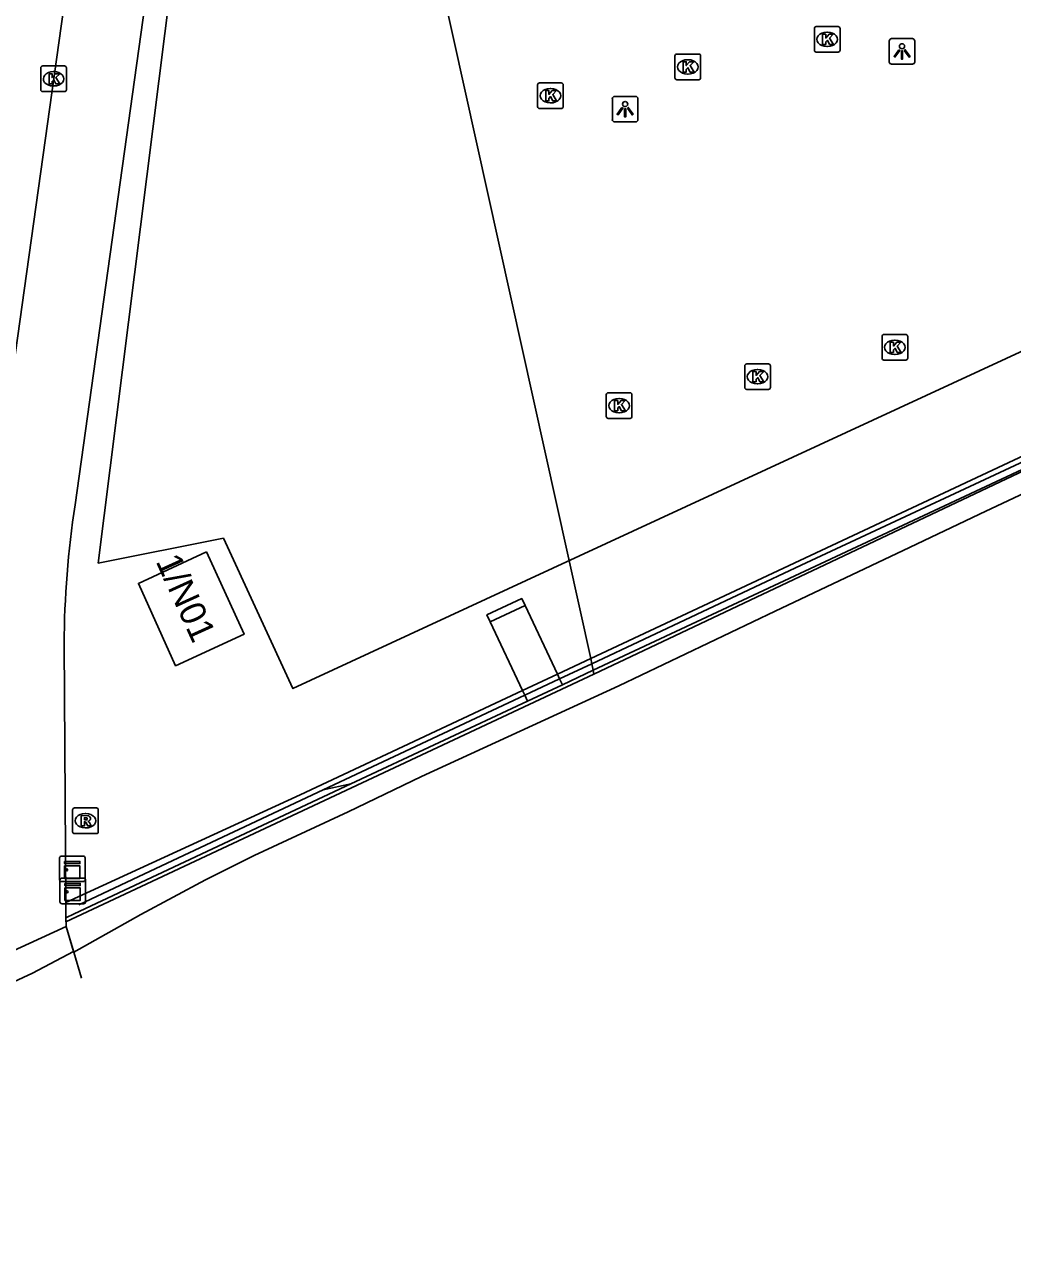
# Model space of a CAD drawing. Extents: x 160806 to 161707, y 383697 to 384148.
# Drawn here: x 161284.05 to 161322.57, y 383743.17 to 383791.51 of the extents above; entities that cross this region are included whole.
import ezdxf

# ---------------------------------------------------------------- set-up
doc = ezdxf.new("R2010")
doc.units = 0
for name, color, linetype in [('IMGEO_Dek', 7, 'Continuous'), ('IMGEO_Fietspad_open', 7, 'Continuous'), ('IMGEO_Groenvoorziening', 7, 'Continuous'), ('IMGEO_Hek', 7, 'Continuous'), ('IMGEO_Kast', 7, 'Continuous'), ('IMGEO_Kolk', 7, 'Continuous'), ('IMGEO_Lichtpunt', 7, 'Continuous'), ('IMGEO_Muur', 7, 'Continuous'), ('IMGEO_Pand', 7, 'Continuous'), ('IMGEO_Pand_nummerreeks', 7, 'Continuous'), ('IMGEO_Pand_vergunning_verleend', 7, 'Continuous'), ('IMGEO_Rioolput', 7, 'Continuous'), ('IMGEO_Spoorbaan_halfverhard', 7, 'Continuous'), ('IMGEO_Spoorbaan_open', 7, 'Continuous'), ('IMGEO_Terreindeel_gesloten', 7, 'Continuous'), ('IMGEO_Voetgangersgebied_open', 7, 'Continuous'), ('IMGEO_Voetpad_op_trap', 7, 'Continuous'), ('IMGEO_Voetpad_open', 7, 'Continuous')]:
    doc.layers.add(name, color=color, linetype=linetype)

msp = doc.modelspace()

# ---------------------------------------------------------------- linework, layer by layer
at = {"layer": 'IMGEO_Dek'}
msp.add_lwpolyline([(161302.206, 383768.201), (161303.47, 383765.52), (161303.556, 383765.337), (161303.663, 383765.111), (161305.021, 383765.747), (161304.913, 383765.977), (161304.828, 383766.158), (161303.562, 383768.841), (161303.434, 383769.112), (161302.078, 383768.472)], close=True, dxfattribs=at)
at = {"layer": 'IMGEO_Fietspad_open'}
msp.add_lwpolyline([(161288.857, 383815.733), (161288.794, 383815.268), (161282.95, 383773.511)], dxfattribs=at)
at = {"layer": 'IMGEO_Groenvoorziening'}
for points in [[(161306.227, 383766.312), (161344.529, 383784.251), (161345.081, 383784.51), (161345.678, 383784.79), (161353.357, 383788.389)], [(161302.206, 383768.201), (161303.562, 383768.841), (161303.434, 383769.112), (161302.078, 383768.472), (161302.206, 383768.201)], [(161306.126, 383766.767), (161304.828, 383766.158), (161303.47, 383765.52), (161294.794, 383761.449), (161285.649, 383757.252)], [(161306.17, 383766.569), (161306.126, 383766.767)], [(161285.653, 383756.655), (161285.978, 383756.8), (161296.767, 383761.881)]]:
    msp.add_lwpolyline(points, dxfattribs=at)
at = {"layer": 'IMGEO_Hek'}
for points in [[(161304.913, 383765.977), (161306.17, 383766.569), (161314.338, 383770.42), (161324.98, 383775.393), (161337.778, 383781.392), (161350.576, 383787.419), (161357.031, 383790.441), (161365.479, 383794.338), (161372.031, 383797.151), (161378.634, 383799.703), (161383.104, 383801.204), (161385.56, 383801.947)], [(161303.556, 383765.337), (161303.47, 383765.52), (161302.206, 383768.201), (161302.078, 383768.472), (161303.434, 383769.112), (161303.562, 383768.841), (161304.828, 383766.158), (161304.913, 383765.977)], [(161303.556, 383765.337), (161297.189, 383762.349), (161295.69, 383761.645), (161288.711, 383758.369), (161286.158, 383757.158)]]:
    msp.add_lwpolyline(points, dxfattribs=at)
at = {"layer": 'IMGEO_Kast'}
for p, q in [((161285.477, 383759.062), (161286.318, 383759.062)), ((161286.318, 383759.062), (161285.477, 383759.062)), ((161285.402, 383758.137), (161285.402, 383758.978)), ((161285.402, 383758.978), (161285.402, 383758.137)), ((161286.402, 383758.987), (161286.402, 383758.146)), ((161286.402, 383758.146), (161286.402, 383758.987)), ((161285.417, 383757.277), (161285.417, 383758.118)), ((161285.417, 383758.118), (161285.417, 383757.277)), ((161285.492, 383758.202), (161286.333, 383758.202)), ((161286.333, 383758.202), (161285.492, 383758.202)), ((161286.417, 383758.127), (161286.417, 383757.286)), ((161286.417, 383757.286), (161286.417, 383758.127)), ((161286.327, 383758.062), (161285.486, 383758.062)), ((161285.486, 383758.062), (161286.327, 383758.062)), ((161286.342, 383757.202), (161285.501, 383757.202)), ((161285.501, 383757.202), (161286.342, 383757.202))]:
    msp.add_line(p, q, dxfattribs=at)
for points in [[(161285.597, 383758.852), (161286.197, 383758.852), (161286.197, 383758.767), (161285.597, 383758.767), (161285.597, 383758.852)], [(161285.597, 383758.677), (161286.197, 383758.677), (161286.197, 383758.188), (161285.597, 383758.188), (161285.597, 383758.677)], [(161285.612, 383757.992), (161286.212, 383757.992), (161286.212, 383757.907), (161285.612, 383757.907), (161285.612, 383757.992)], [(161285.612, 383757.817), (161286.212, 383757.817), (161286.212, 383757.328), (161285.612, 383757.328), (161285.612, 383757.817)]]:
    msp.add_lwpolyline(points, dxfattribs=at)
for centre in [(161285.681, 383758.526), (161285.696, 383757.666)]:
    msp.add_circle(centre, 0.0377, dxfattribs=at)
for centre, start, end in [((161285.48, 383758.984), 92.4484, 184.2845), ((161285.48, 383758.984), 92.4484, 184.2845), ((161286.324, 383758.984), 2.4484, 94.2845), ((161286.324, 383758.984), 2.4484, 94.2845), ((161285.48, 383758.14), 182.4484, 274.2845), ((161285.48, 383758.14), 182.4484, 274.2845), ((161285.495, 383758.124), 92.4484, 184.2845), ((161285.495, 383758.124), 92.4484, 184.2845), ((161286.324, 383758.14), 272.4484, 4.2845), ((161286.324, 383758.14), 272.4484, 4.2845), ((161286.339, 383758.124), 2.4484, 94.2845), ((161286.339, 383758.124), 2.4484, 94.2845), ((161285.495, 383757.28), 182.4484, 274.2845), ((161285.495, 383757.28), 182.4484, 274.2845), ((161286.339, 383757.28), 272.4484, 4.2845), ((161286.339, 383757.28), 272.4484, 4.2845)]:
    msp.add_arc(centre, 0.0779, start, end, dxfattribs=at)
at = {"layer": 'IMGEO_Kolk'}
for p, q in [((161314.927, 383791.444), (161315.779, 383791.444)), ((161314.852, 383790.518), (161314.852, 383791.37)), ((161315.34, 383791.224), (161315.365, 383791.224)), ((161315.853, 383791.37), (161315.853, 383790.518)), ((161315.363, 383790.664), (161315.338, 383790.664)), ((161309.411, 383789.442), (161309.411, 383790.294)), ((161309.486, 383790.368), (161310.338, 383790.368)), ((161309.899, 383790.148), (161309.924, 383790.148)), ((161310.412, 383790.294), (161310.412, 383789.442)), ((161315.779, 383790.444), (161314.927, 383790.444)), ((161284.671, 383788.977), (161284.671, 383789.829)), ((161284.746, 383789.903), (161285.598, 383789.903)), ((161285.159, 383789.683), (161285.184, 383789.683)), ((161285.672, 383789.829), (161285.672, 383788.977)), ((161309.922, 383789.588), (161309.897, 383789.588)), ((161285.182, 383789.123), (161285.157, 383789.123)), ((161304.052, 383788.316), (161304.052, 383789.168)), ((161304.127, 383789.242), (161304.979, 383789.242)), ((161304.54, 383789.022), (161304.565, 383789.022)), ((161305.053, 383789.168), (161305.053, 383788.316)), ((161310.338, 383789.368), (161309.486, 383789.368)), ((161285.598, 383788.903), (161284.746, 383788.903)), ((161304.979, 383788.242), (161304.127, 383788.242)), ((161304.563, 383788.462), (161304.538, 383788.462)), ((161317.491, 383778.495), (161317.491, 383779.347)), ((161317.566, 383779.421), (161318.418, 383779.421)), ((161318.492, 383779.347), (161318.492, 383778.495)), ((161317.979, 383779.201), (161318.004, 383779.201)), ((161318.418, 383778.421), (161317.566, 383778.421)), ((161318.002, 383778.641), (161317.977, 383778.641)), ((161312.135, 383777.349), (161312.135, 383778.201)), ((161312.21, 383778.275), (161313.062, 383778.275)), ((161312.623, 383778.055), (161312.648, 383778.055)), ((161313.136, 383778.201), (161313.136, 383777.349)), ((161312.646, 383777.495), (161312.621, 383777.495)), ((161306.733, 383776.218), (161306.733, 383777.07)), ((161306.808, 383777.144), (161307.66, 383777.144)), ((161307.734, 383777.07), (161307.734, 383776.218)), ((161313.062, 383777.275), (161312.21, 383777.275)), ((161307.221, 383776.924), (161307.246, 383776.924)), ((161307.66, 383776.144), (161306.808, 383776.144)), ((161307.244, 383776.364), (161307.219, 383776.364))]:
    msp.add_line(p, q, dxfattribs=at)
for points in [[(161314.927, 383791.444), (161315.779, 383791.444)], [(161314.852, 383790.518), (161314.852, 383791.37)], [(161315.173, 383791.144), (161315.296, 383791.144), (161315.296, 383790.993), (161315.426, 383791.144), (161315.59, 383791.144), (161315.444, 383790.993), (161315.597, 383790.744), (161315.445, 383790.744), (161315.36, 383790.908), (161315.296, 383790.841), (161315.296, 383790.744), (161315.173, 383790.744), (161315.173, 383791.144)], [(161315.853, 383791.37), (161315.853, 383790.518)], [(161309.411, 383789.442), (161309.411, 383790.294)], [(161309.486, 383790.368), (161310.338, 383790.368)], [(161309.732, 383790.068), (161309.855, 383790.068), (161309.855, 383789.917), (161309.985, 383790.068), (161310.149, 383790.068), (161310.003, 383789.917), (161310.156, 383789.668), (161310.004, 383789.668), (161309.919, 383789.832), (161309.855, 383789.765), (161309.855, 383789.668), (161309.732, 383789.668), (161309.732, 383790.068)], [(161310.412, 383790.294), (161310.412, 383789.442)], [(161315.779, 383790.444), (161314.927, 383790.444)], [(161284.671, 383788.977), (161284.671, 383789.829)], [(161284.746, 383789.903), (161285.598, 383789.903)], [(161284.992, 383789.603), (161285.115, 383789.603), (161285.115, 383789.452), (161285.245, 383789.603), (161285.409, 383789.603), (161285.263, 383789.452), (161285.416, 383789.203), (161285.264, 383789.203), (161285.179, 383789.367), (161285.115, 383789.3), (161285.115, 383789.203), (161284.992, 383789.203), (161284.992, 383789.603)], [(161285.672, 383789.829), (161285.672, 383788.977)], [(161304.052, 383788.316), (161304.052, 383789.168)], [(161304.127, 383789.242), (161304.979, 383789.242)], [(161305.053, 383789.168), (161305.053, 383788.316)], [(161310.338, 383789.368), (161309.486, 383789.368)], [(161285.598, 383788.903), (161284.746, 383788.903)], [(161304.373, 383788.942), (161304.496, 383788.942), (161304.496, 383788.791), (161304.626, 383788.942), (161304.79, 383788.942), (161304.644, 383788.791), (161304.797, 383788.542), (161304.645, 383788.542), (161304.56, 383788.706), (161304.496, 383788.639), (161304.496, 383788.542), (161304.373, 383788.542), (161304.373, 383788.942)], [(161304.979, 383788.242), (161304.127, 383788.242)], [(161317.491, 383778.495), (161317.491, 383779.347)], [(161317.566, 383779.421), (161318.418, 383779.421)], [(161318.492, 383779.347), (161318.492, 383778.495)], [(161317.812, 383779.121), (161317.935, 383779.121), (161317.935, 383778.97), (161318.065, 383779.121), (161318.229, 383779.121), (161318.083, 383778.97), (161318.236, 383778.721), (161318.084, 383778.721), (161317.999, 383778.885), (161317.935, 383778.818), (161317.935, 383778.721), (161317.812, 383778.721), (161317.812, 383779.121)], [(161318.418, 383778.421), (161317.566, 383778.421)], [(161312.135, 383777.349), (161312.135, 383778.201)], [(161312.21, 383778.275), (161313.062, 383778.275)], [(161312.456, 383777.975), (161312.579, 383777.975), (161312.579, 383777.824), (161312.709, 383777.975), (161312.873, 383777.975), (161312.727, 383777.824), (161312.88, 383777.575), (161312.728, 383777.575), (161312.643, 383777.739), (161312.579, 383777.672), (161312.579, 383777.575), (161312.456, 383777.575), (161312.456, 383777.975)], [(161313.136, 383778.201), (161313.136, 383777.349)], [(161306.733, 383776.218), (161306.733, 383777.07)], [(161306.808, 383777.144), (161307.66, 383777.144)], [(161307.734, 383777.07), (161307.734, 383776.218)], [(161313.062, 383777.275), (161312.21, 383777.275)], [(161307.054, 383776.844), (161307.177, 383776.844), (161307.177, 383776.693), (161307.307, 383776.844), (161307.471, 383776.844), (161307.325, 383776.693), (161307.478, 383776.444), (161307.326, 383776.444), (161307.241, 383776.608), (161307.177, 383776.541), (161307.177, 383776.444), (161307.054, 383776.444), (161307.054, 383776.844)], [(161307.66, 383776.144), (161306.808, 383776.144)]]:
    msp.add_lwpolyline(points, dxfattribs=at)
for centre, start, end in [((161314.929, 383791.368), 91.552, 178.448), ((161314.929, 383791.368), 91.552, 178.448), ((161315.777, 383791.368), 1.552, 88.448), ((161315.777, 383791.368), 1.552, 88.448), ((161314.929, 383790.52), 181.552, 268.448), ((161314.929, 383790.52), 181.552, 268.448), ((161315.777, 383790.52), 271.552, 358.448), ((161315.777, 383790.52), 271.552, 358.448), ((161309.488, 383790.292), 91.552, 178.448), ((161309.488, 383790.292), 91.552, 178.448), ((161310.336, 383790.292), 1.552, 88.448), ((161310.336, 383790.292), 1.552, 88.448), ((161284.748, 383789.827), 91.552, 178.448), ((161284.748, 383789.827), 91.552, 178.448), ((161285.596, 383789.827), 1.552, 88.448), ((161285.596, 383789.827), 1.552, 88.448), ((161304.129, 383789.166), 91.552, 178.448), ((161304.129, 383789.166), 91.552, 178.448), ((161304.977, 383789.166), 1.552, 88.448), ((161304.977, 383789.166), 1.552, 88.448), ((161309.488, 383789.444), 181.552, 268.448), ((161309.488, 383789.444), 181.552, 268.448), ((161310.336, 383789.444), 271.552, 358.448), ((161310.336, 383789.444), 271.552, 358.448), ((161284.748, 383788.979), 181.552, 268.448), ((161284.748, 383788.979), 181.552, 268.448), ((161285.596, 383788.979), 271.552, 358.448), ((161285.596, 383788.979), 271.552, 358.448), ((161304.129, 383788.318), 181.552, 268.448), ((161304.129, 383788.318), 181.552, 268.448), ((161304.977, 383788.318), 271.552, 358.448), ((161304.977, 383788.318), 271.552, 358.448), ((161317.568, 383779.345), 91.552, 178.448), ((161317.568, 383779.345), 91.552, 178.448), ((161318.416, 383779.345), 1.552, 88.448), ((161318.416, 383779.345), 1.552, 88.448), ((161317.568, 383778.497), 181.552, 268.448), ((161317.568, 383778.497), 181.552, 268.448), ((161318.416, 383778.497), 271.552, 358.448), ((161318.416, 383778.497), 271.552, 358.448), ((161312.212, 383778.199), 91.552, 178.448), ((161312.212, 383778.199), 91.552, 178.448), ((161313.06, 383778.199), 1.552, 88.448), ((161313.06, 383778.199), 1.552, 88.448), ((161306.81, 383777.068), 91.552, 178.448), ((161306.81, 383777.068), 91.552, 178.448), ((161307.658, 383777.068), 1.552, 88.448), ((161307.658, 383777.068), 1.552, 88.448), ((161312.212, 383777.351), 181.552, 268.448), ((161312.212, 383777.351), 181.552, 268.448), ((161313.06, 383777.351), 271.552, 358.448), ((161313.06, 383777.351), 271.552, 358.448), ((161306.81, 383776.22), 181.552, 268.448), ((161306.81, 383776.22), 181.552, 268.448), ((161307.658, 383776.22), 271.552, 358.448), ((161307.658, 383776.22), 271.552, 358.448)]:
    msp.add_arc(centre, 0.0765, start, end, dxfattribs=at)
for centre, major_axis, ratio, start_param, end_param in [((161315.339, 383790.944), (-0.387, 0.002), 0.722429, 4.712389, 7.853982), ((161315.364, 383790.944), (-0.39, 0.002), 0.717154, 1.570796, 4.712389), ((161309.898, 383789.868), (-0.387, 0.002), 0.722429, 4.712389, 7.853982), ((161309.923, 383789.868), (-0.39, 0.002), 0.717154, 1.570796, 4.712389), ((161285.158, 383789.403), (-0.387, 0.002), 0.722429, 4.712389, 7.853982), ((161285.183, 383789.403), (-0.39, 0.002), 0.717154, 1.570796, 4.712389), ((161304.539, 383788.742), (-0.387, 0.002), 0.722429, 4.712389, 7.853982), ((161304.564, 383788.742), (-0.39, 0.002), 0.717154, 1.570796, 4.712389), ((161317.978, 383778.921), (-0.387, 0.002), 0.722429, 4.712389, 7.853982), ((161318.003, 383778.921), (-0.39, 0.002), 0.717154, 1.570796, 4.712389), ((161312.622, 383777.775), (-0.387, 0.002), 0.722429, 4.712389, 7.853982), ((161312.647, 383777.775), (-0.39, 0.002), 0.717154, 1.570796, 4.712389), ((161307.22, 383776.644), (-0.387, 0.002), 0.722429, 4.712389, 7.853982), ((161307.245, 383776.644), (-0.39, 0.002), 0.717154, 1.570796, 4.712389)]:
    msp.add_ellipse(centre, major_axis=major_axis, ratio=ratio, start_param=start_param, end_param=end_param, dxfattribs=at)
at = {"layer": 'IMGEO_Lichtpunt'}
for p, q in [((161318.673, 383790.971), (161317.865, 383790.971)), ((161318.673, 383790.971), (161317.865, 383790.971)), ((161317.771, 383790.876), (161317.771, 383790.069)), ((161317.771, 383790.876), (161317.771, 383790.069)), ((161318.767, 383790.069), (161318.767, 383790.876)), ((161318.767, 383790.069), (161318.767, 383790.876)), ((161317.865, 383789.975), (161318.673, 383789.975)), ((161317.865, 383789.975), (161318.673, 383789.975)), ((161306.969, 383788.621), (161306.969, 383787.814)), ((161306.969, 383788.621), (161306.969, 383787.814)), ((161307.871, 383788.716), (161307.063, 383788.716)), ((161307.871, 383788.716), (161307.063, 383788.716)), ((161307.965, 383787.814), (161307.965, 383788.621)), ((161307.965, 383787.814), (161307.965, 383788.621)), ((161307.063, 383787.72), (161307.871, 383787.72)), ((161307.063, 383787.72), (161307.871, 383787.72))]:
    msp.add_line(p, q, dxfattribs=at)
for points in [[(161318.145, 383790.54), (161318.184, 383790.512), (161317.996, 383790.25), (161317.958, 383790.277), (161318.145, 383790.54)], [(161318.247, 383790.492), (161318.294, 383790.492), (161318.294, 383790.17), (161318.247, 383790.17), (161318.247, 383790.492)], [(161318.357, 383790.512), (161318.395, 383790.539), (161318.582, 383790.277), (161318.543, 383790.249), (161318.357, 383790.512)], [(161307.343, 383788.285), (161307.382, 383788.257), (161307.194, 383787.995), (161307.156, 383788.022), (161307.343, 383788.285)], [(161307.445, 383788.237), (161307.492, 383788.237), (161307.492, 383787.915), (161307.445, 383787.915), (161307.445, 383788.237)], [(161307.555, 383788.257), (161307.593, 383788.284), (161307.78, 383788.022), (161307.741, 383787.994), (161307.555, 383788.257)]]:
    msp.add_lwpolyline(points, dxfattribs=at)
for centre in [(161318.27, 383790.674), (161307.468, 383788.419)]:
    msp.add_circle(centre, 0.0994, dxfattribs=at)
for centre, start, end in [((161317.865, 383790.876), 90, 180), ((161317.865, 383790.876), 90, 180), ((161318.673, 383790.876), 0, 90), ((161318.673, 383790.876), 0, 90), ((161317.865, 383790.069), 180, 270), ((161317.865, 383790.069), 180, 270), ((161318.673, 383790.069), 270, 0), ((161318.673, 383790.069), 270, 360), ((161307.063, 383788.621), 90, 180), ((161307.063, 383788.621), 90, 180), ((161307.871, 383788.621), 0, 90), ((161307.871, 383788.621), 0, 90), ((161307.063, 383787.814), 180, 270), ((161307.063, 383787.814), 180, 270), ((161307.871, 383787.814), 270, 0), ((161307.871, 383787.814), 270, 360)]:
    msp.add_arc(centre, 0.0946, start, end, dxfattribs=at)
at = {"layer": 'IMGEO_Muur'}
for points in [[(161285.653, 383756.655), (161285.978, 383756.8), (161296.767, 383761.881), (161303.663, 383765.111), (161305.021, 383765.747), (161306.227, 383766.312), (161344.529, 383784.251), (161345.081, 383784.51), (161345.678, 383784.79)], [(161336.721, 383780.594), (161306.249, 383766.164)], [(161306.17, 383766.569), (161304.913, 383765.977), (161303.556, 383765.337), (161297.189, 383762.349), (161295.69, 383761.645), (161296.767, 383761.881)], [(161296.767, 383761.881), (161303.663, 383765.111), (161305.021, 383765.747), (161306.227, 383766.312)], [(161306.227, 383766.312), (161306.17, 383766.569)], [(161306.249, 383766.164), (161306.217, 383766.307)], [(161306.249, 383766.164), (161285.654, 383756.492)]]:
    msp.add_lwpolyline(points, dxfattribs=at)
at = {"layer": 'IMGEO_Pand'}
msp.add_lwpolyline([(161291.132, 383770.935), (161292.601, 383767.718), (161289.931, 383766.49), (161288.478, 383769.707), (161291.132, 383770.935)], dxfattribs=at)
at = {"layer": 'IMGEO_Pand_vergunning_verleend'}
msp.add_lwpolyline([(161286.905, 383770.489), (161291.413, 383806.28), (161303.76, 383808.96), (161303.031, 383812.451), (161323.52, 383816.728), (161325.87, 383813.583), (161332.156, 383815.078), (161338.096, 383790.101), (161336.982, 383788.652), (161333.878, 383784.616), (161329.619, 383781.849), (161303.612, 383769.813), (161294.509, 383765.6), (161291.793, 383771.467), (161286.905, 383770.489)], dxfattribs=at)
at = {"layer": 'IMGEO_Rioolput'}
for p, q in [((161285.912, 383760.013), (161285.912, 383760.865)), ((161285.987, 383760.939), (161286.839, 383760.939)), ((161286.4, 383760.719), (161286.425, 383760.719)), ((161286.913, 383760.865), (161286.913, 383760.013)), ((161286.423, 383760.159), (161286.398, 383760.159)), ((161286.839, 383759.939), (161285.987, 383759.939))]:
    msp.add_line(p, q, dxfattribs=at)
for points in [[(161285.912, 383760.013), (161285.912, 383760.865)], [(161285.987, 383760.939), (161286.839, 383760.939)], [(161286.501, 383760.637), (161286.249, 383760.639), (161286.249, 383760.239)], [(161286.427, 383760.558), (161286.373, 383760.558), (161286.373, 383760.477)], [(161286.913, 383760.865), (161286.913, 383760.013)], [(161286.249, 383760.239), (161286.373, 383760.239), (161286.373, 383760.401), (161286.384, 383760.401)], [(161286.373, 383760.477), (161286.425, 383760.477)], [(161286.431, 383760.372), (161286.502, 383760.239), (161286.642, 383760.239), (161286.577, 383760.365)], [(161286.839, 383759.939), (161285.987, 383759.939)]]:
    msp.add_lwpolyline(points, dxfattribs=at)
for centre, radius, start, end in [((161285.989, 383760.863), 0.0765, 91.552, 178.448), ((161285.989, 383760.863), 0.0765, 91.552, 178.448), ((161286.433, 383760.462), 0.0964, 77.0061, 93.1865), ((161286.447, 383760.519), 0.0378, 276.6634, 79.6772), ((161286.5, 383760.527), 0.109, 350.3612, 89.416), ((161286.498, 383760.527), 0.112, 277.5842, 350.9817), ((161286.837, 383760.863), 0.0765, 1.552, 88.448), ((161286.837, 383760.863), 0.0765, 1.552, 88.448), ((161285.989, 383760.015), 0.0765, 181.552, 268.448), ((161285.989, 383760.015), 0.0765, 181.552, 268.448), ((161286.383, 383760.348), 0.0533, 26.0293, 88.6989), ((161286.409, 383760.666), 0.19, 274.7715, 282.9687), ((161286.482, 383760.312), 0.108, 29.5134, 73.7905), ((161286.837, 383760.015), 0.0765, 271.552, 358.448), ((161286.837, 383760.015), 0.0765, 271.552, 358.448)]:
    msp.add_arc(centre, radius, start, end, dxfattribs=at)
for centre, major_axis, ratio, start_param, end_param in [((161286.399, 383760.439), (-0.387, 0.002), 0.722429, 4.712389, 7.853982), ((161286.424, 383760.439), (-0.39, 0.002), 0.717154, 1.570796, 4.712389)]:
    msp.add_ellipse(centre, major_axis=major_axis, ratio=ratio, start_param=start_param, end_param=end_param, dxfattribs=at)
at = {"layer": 'IMGEO_Spoorbaan_halfverhard'}
for points in [[(161390.935, 383802.444), (161386.08, 383801.266), (161382.118, 383800.16), (161375.55, 383797.589), (161371.195, 383795.912), (161367.786, 383794.395), (161361.592, 383791.682), (161358.915, 383790.513), (161353.739, 383787.835), (161348.742, 383785.497), (161341.727, 383782.043), (161334.24, 383778.465), (161328.287, 383775.698), (161321.541, 383772.521), (161318.31, 383770.995), (161313.322, 383768.622), (161307.226, 383765.703), (161299.525, 383762.169), (161296.669, 383760.786), (161293.001, 383759.082), (161291.091, 383758.136), (161288.575, 383756.779), (161285.955, 383755.31)], [(161285.955, 383755.31), (161286.26, 383754.291)]]:
    msp.add_lwpolyline(points, dxfattribs=at)
at = {"layer": 'IMGEO_Spoorbaan_open'}
msp.add_lwpolyline([(161285.947, 383755.338), (161284.345, 383754.49), (161268.558, 383747.163), (161262.971, 383744.495), (161259.937, 383743.21), (161257.671, 383742.18)], dxfattribs=at)
at = {"layer": 'IMGEO_Terreindeel_gesloten'}
msp.add_lwpolyline([(161285.947, 383755.338), (161285.655, 383756.314), (161257.339, 383743.293), (161257.671, 383742.18)], dxfattribs=at)
at = {"layer": 'IMGEO_Voetgangersgebied_open'}
for points in [[(161306.126, 383766.767), (161298.089, 383803.089), (161297.905, 383804.094)], [(161306.126, 383766.767), (161331.617, 383778.728), (161344.422, 383784.744), (161344.962, 383784.997), (161345.557, 383785.277)]]:
    msp.add_lwpolyline(points, dxfattribs=at)
at = {"layer": 'IMGEO_Voetpad_op_trap'}
msp.add_lwpolyline([(161302.206, 383768.201), (161303.47, 383765.52), (161303.556, 383765.337), (161303.663, 383765.111), (161305.021, 383765.747), (161304.913, 383765.977), (161304.828, 383766.158), (161303.562, 383768.841), (161303.434, 383769.112), (161302.078, 383768.472), (161302.206, 383768.201)], dxfattribs=at)
at = {"layer": 'IMGEO_Voetpad_open'}
for points in [[(161286.008, 383772.772), (161291.849, 383814.638)], [(161285.649, 383757.252), (161285.58, 383767.33)], [(161285.653, 383756.655), (161285.649, 383757.252)], [(161285.955, 383755.31), (161285.655, 383756.314), (161285.653, 383756.655)]]:
    msp.add_lwpolyline(points, dxfattribs=at)
msp.add_arc((161323.898, 383767.054), 38.319, 171.4186, 179.5876, dxfattribs=at)

# ---------------------------------------------------------------- texts
at = {"layer": 'IMGEO_Pand_nummerreeks'}
msp.add_text('1/N01', height=1, rotation=294.425, dxfattribs=at).set_placement((161289.143, 383770.57))

doc.saveas('drawing.dxf')
